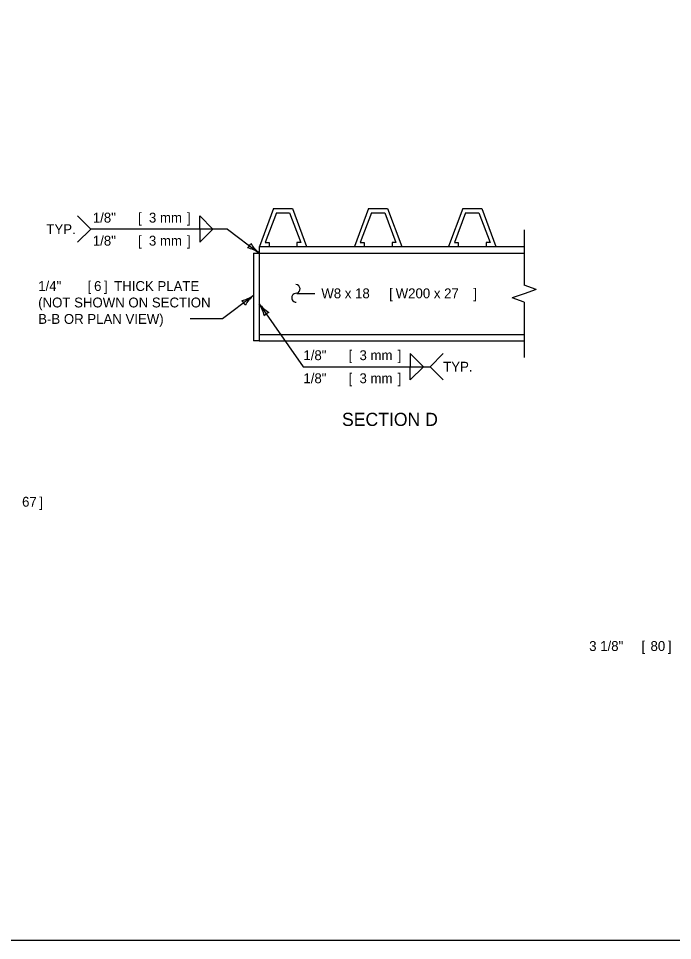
# Model space of a CAD drawing. Extents: x 49991.4 to 50021, y 49987.6 to 50011.4.
# Drawn here: x 50006.02 to 50010, y 49987.8 to 49993.4 of the extents above; entities that cross this region are included whole.
import ezdxf

# ---------------------------------------------------------------- set-up
doc = ezdxf.new("R2010")
doc.units = 0
for name, color, linetype in [('Level 1', 7, 'Continuous'), ('Level 2', 7, 'Continuous'), ('Level 3', 7, 'Continuous'), ('Level 6', 7, 'Continuous')]:
    doc.layers.add(name, color=color, linetype=linetype)

msp = doc.modelspace()

# ---------------------------------------------------------------- linework, layer by layer
at = {"layer": 'Level 1'}
for p, q in [((50007.5727, 49992.2467), (50007.4865, 49992.0165)), ((50007.5727, 49992.2467), (50007.6877, 49992.2467)), ((50007.6877, 49992.2467), (50007.774, 49992.0165)), ((50008.1507, 49992.2467), (50008.0645, 49992.0165)), ((50008.1507, 49992.2467), (50008.2657, 49992.2467)), ((50008.2657, 49992.2467), (50008.352, 49992.0165)), ((50008.7226, 49992.2467), (50008.6364, 49992.0165)), ((50008.7226, 49992.2467), (50008.8376, 49992.2467)), ((50008.8376, 49992.2467), (50008.9238, 49992.0165)), ((50007.59, 49992.2217), (50007.522, 49992.0401)), ((50007.59, 49992.2217), (50007.6704, 49992.2217)), ((50007.6704, 49992.2217), (50007.7384, 49992.0401)), ((50008.168, 49992.2217), (50008.1, 49992.0401)), ((50008.168, 49992.2217), (50008.2484, 49992.2217)), ((50008.2484, 49992.2217), (50008.3164, 49992.0401)), ((50008.7399, 49992.2217), (50008.6719, 49992.0401)), ((50008.7399, 49992.2217), (50008.8203, 49992.2217)), ((50008.8203, 49992.2217), (50008.8883, 49992.0401)), ((50007.4861, 49992.0165), (50009.0955, 49992.0165)), ((50007.4861, 49992.0165), (50007.4861, 49991.4421)), ((50007.522, 49992.0401), (50007.5456, 49992.0401)), ((50007.5456, 49992.0401), (50007.5456, 49992.0165)), ((50007.7384, 49992.0401), (50007.7149, 49992.0401)), ((50007.7149, 49992.0401), (50007.7149, 49992.0165)), ((50008.1, 49992.0401), (50008.1236, 49992.0401)), ((50008.1236, 49992.0401), (50008.1236, 49992.0165)), ((50008.3164, 49992.0401), (50008.2929, 49992.0401)), ((50008.2929, 49992.0401), (50008.2929, 49992.0165)), ((50008.6719, 49992.0401), (50008.6954, 49992.0401)), ((50008.6954, 49992.0401), (50008.6954, 49992.0165)), ((50008.8883, 49992.0401), (50008.8648, 49992.0401)), ((50008.8648, 49992.0401), (50008.8648, 49992.0165)), ((50007.4511, 49991.9765), (50007.4511, 49991.4421)), ((50007.4511, 49991.9765), (50009.0955, 49991.9765)), ((50007.4861, 49991.4421), (50007.4511, 49991.4421)), ((50007.4861, 49991.4821), (50009.0955, 49991.4821)), ((50007.4861, 49991.4421), (50009.0955, 49991.4421))]:
    msp.add_line(p, q, dxfattribs=at)
msp.add_lwpolyline([(49999.3835, 49998.9992), (50016.7501, 49998.9992), (50016.7501, 49987.7988), (49999.3835, 49987.7988)], close=True, dxfattribs=at)
at = {"layer": 'Level 3'}
for p, q in [((50006.3815, 49992.2016), (50006.4622, 49992.1216)), ((50007.1243, 49992.2016), (50007.2043, 49992.1216)), ((50007.1243, 49992.1216), (50007.1243, 49992.2016)), ((50006.3825, 49992.0419), (50006.4622, 49992.1216)), ((50007.2923, 49992.1216), (50006.4622, 49992.1216)), ((50007.1243, 49992.1216), (50007.1243, 49992.0416)), ((50007.1243, 49992.0416), (50007.2043, 49992.1216)), ((50007.2923, 49992.1216), (50007.4861, 49991.9765)), ((50007.7134, 49991.7316), (50007.8232, 49991.7316)), ((50007.4511, 49991.7193), (50007.2636, 49991.5759)), ((50007.4861, 49991.6679), (50007.7537, 49991.2856)), ((50007.2636, 49991.5759), (50007.0661, 49991.5759)), ((50008.4037, 49991.3656), (50008.4037, 49991.2856)), ((50008.4037, 49991.3656), (50008.4837, 49991.2856)), ((50008.5237, 49991.2856), (50008.6037, 49991.3656)), ((50007.7537, 49991.2856), (50008.5237, 49991.2856)), ((50008.4037, 49991.2056), (50008.4037, 49991.2856)), ((50008.4037, 49991.2056), (50008.4837, 49991.2856)), ((50008.5237, 49991.2856), (50008.6037, 49991.2056))]:
    msp.add_line(p, q, dxfattribs=at)
for centre, radius, start, end in [((50007.3828, 49992.0526), 0.0548, 305.7451, 341.4675), ((50007.3572, 49991.7824), 0.233, 56.4336, 75.6835), ((50007.6252, 49992.1499), 0.2223, 211.0623, 231.2458), ((50007.7067, 49991.758), 0.0272, 284.25, 86.6087), ((50007.7107, 49991.7046), 0.0272, 84.3293, 270), ((50007.3234, 49991.9013), 0.2223, 284.8632, 305.0467), ((50007.3492, 49991.6414), 0.0548, 19.546, 55.2683), ((50007.6015, 49991.5415), 0.233, 130.2345, 149.4843), ((50007.2988, 49991.548), 0.2223, 12.454, 32.6375), ((50007.6701, 49991.8108), 0.233, 217.8253, 237.0752), ((50007.5596, 49991.5628), 0.0548, 107.1368, 142.8592)]:
    msp.add_arc(centre, radius, start, end, dxfattribs=at)
at = {"layer": 'Level 6'}
for p, q in [((50009.0955, 49992.1165), (50009.0955, 49991.7811)), ((50009.1686, 49991.7552), (50009.0955, 49991.7811)), ((50009.0955, 49991.7293), (50009.0224, 49991.7034)), ((50009.1686, 49991.7552), (50009.0955, 49991.7293)), ((50009.0955, 49991.6775), (50009.0224, 49991.7034)), ((50009.0955, 49991.6775), (50009.0955, 49991.3421))]:
    msp.add_line(p, q, dxfattribs=at)

# ---------------------------------------------------------------- texts
at = {"layer": 'Level 2'}
for s, height, p in [(' 1/8" ', 0.06, (50006.4525, 49992.1616)), ('[', 0.06, (50006.7493, 49992.1616)), ('3 mm', 0.06, (50006.8156, 49992.1616)), (']', 0.06, (50007.0469, 49992.1616)), ('TYP.', 0.06, (50006.1926, 49992.0916)), (' 1/8" ', 0.06, (50006.4525, 49992.0216)), ('[', 0.06, (50006.7493, 49992.0216)), ('3 mm', 0.06, (50006.8156, 49992.0216)), (']', 0.06, (50007.0469, 49992.0216)), ('1/4" ', 0.06, (50006.1428, 49991.7459)), ('[', 0.06, (50006.4428, 49991.7459)), ('6', 0.06, (50006.4825, 49991.7459)), (']', 0.06, (50006.5425, 49991.7459)), (' THICK PLATE', 0.06, (50006.5821, 49991.7459)), ('W8 x 18 ', 0.06, (50007.8632, 49991.7016)), ('[', 0.06, (50008.2753, 49991.7016)), ('W200 x 27', 0.06, (50008.315, 49991.7016)), (']', 0.06, (50008.7865, 49991.7016)), ('(NOT SHOWN ON SECTION', 0.06, (50006.1428, 49991.6459)), ('B-B OR PLAN VIEW)', 0.06, (50006.1428, 49991.5459)), (' 1/8" ', 0.06, (50007.732, 49991.3256)), ('[', 0.06, (50008.0288, 49991.3256)), ('3 mm', 0.06, (50008.095, 49991.3256)), (']', 0.06, (50008.3264, 49991.3256)), ('TYP. ', 0.06, (50008.6037, 49991.2556)), (' 1/8" ', 0.06, (50007.732, 49991.1856)), ('[', 0.06, (50008.0288, 49991.1856)), ('3 mm', 0.06, (50008.095, 49991.1856)), (']', 0.06, (50008.3264, 49991.1856)), ('SECTION D', 0.08, (50007.9888, 49990.9258)), ('67', 0.06, (50006.045, 49990.435)), (']', 0.06, (50006.1498, 49990.4337)), ('3 1/8" ', 0.06, (50009.4907, 49989.5586)), ('[', 0.06, (50009.8087, 49989.5586)), ('80', 0.06, (50009.8634, 49989.5586)), (']', 0.06, (50009.9684, 49989.5586))]:
    msp.add_text(s, height=height, dxfattribs=at).set_placement(p)

doc.saveas('drawing.dxf')
